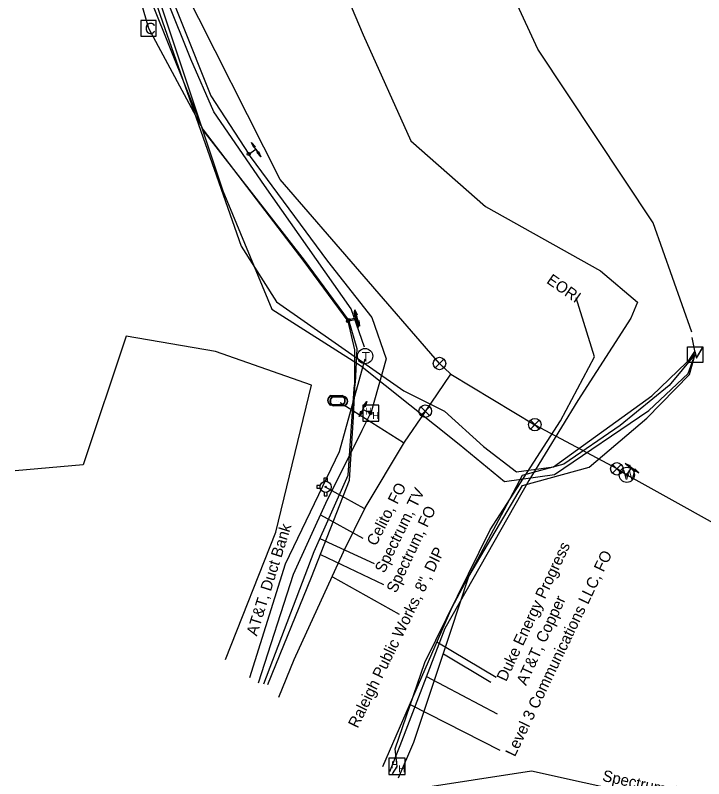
# Model space of a CAD drawing. Extents: x 2070721 to 2083039, y 729290 to 737883.
# Drawn here: x 2080202.5 to 2080447.3, y 733859.2 to 734130.6 of the extents above; entities that cross this region are included whole.
import ezdxf

# ---------------------------------------------------------------- set-up
doc = ezdxf.new("R2010")
doc.units = 0
for name, color, linetype in [('Cogo Default Point CELL', 7, 'Continuous'), ('COGO Default Point Elevation', 7, 'Continuous'), ('COGO Default Point Number', 7, 'Continuous'), ('Exist Utilities Gas UG Line SUE Cogo Point CELL', 7, 'Continuous'), ('Exist Utilities Gas UG Line SUE LOS B Cogo Comment', 7, 'Continuous'), ('Exist Utilities Gas Valve CELL', 7, 'Continuous'), ('Exist Utilities Gas Valve Cogo Elevation', 7, 'Continuous'), ('Exist Utilities Other Unknown UG SUE LOS B Cogo Comment', 7, 'Continuous'), ('Exist Utilities Other Unknown UG SUE LOS B Cogo Elevation', 7, 'Continuous'), ('Exist Utilities Power Pole CELL', 7, 'Continuous'), ('Exist Utilities Power Pole Cogo Elevation', 7, 'Continuous'), ('Exist Utilities Power UG Cable SUE LOS B Cogo Number', 7, 'Continuous'), ('Exist Utilities Telephone Hand Hole Cogo Elevation', 7, 'Continuous'), ('Exist Utilities Telephone Pedestal CELL', 7, 'Continuous'), ('Exist Utilities Telephone Pedestal Cogo Elevation', 7, 'Continuous'), ('Exist Utilities Telephone Pedestal Cogo Number', 7, 'Continuous'), ('Exist Utilities Telephone UG Cable Cogo Point CELL', 7, 'Continuous'), ('Exist Utilities Telephone UG Cable SUE LOS C Cogo Number', 7, 'Continuous'), ('Exist Utilities Telephone UG Cable SUE LOS C Cogo Point CELL', 7, 'Continuous'), ('Exist Utilities Telephone UG FO Cogo Point CELL', 7, 'Continuous'), ('Exist Utilities Telephone UG FO SUE LOS B Cogo Elevation', 7, 'Continuous'), ('Exist Utilities Telephone UG FO SUE LOS B Cogo Number', 7, 'Continuous'), ('Exist Utilities TV Hand Hole CELL', 7, 'Continuous'), ('Exist Utilities TV Pedestal CELL', 7, 'Continuous'), ('Exist Utilities TV Pedestal Cogo Elevation', 7, 'Continuous'), ('Exist Utilities TV UG Cable Cogo Point CELL', 7, 'Continuous'), ('Exist Utilities TV UG Cable SUE LOS C Cogo Comment', 7, 'Continuous'), ('Exist Utilities TV UG Cable SUE LOS C Cogo Elevation', 7, 'Continuous'), ('Exist Utilities TV UG Cable SUE LOS C Cogo Point CELL', 7, 'Continuous'), ('Exist Utilities Water Manhole CELL', 7, 'Continuous'), ('Exist Utilities Water Manhole Cogo Elevation', 7, 'Continuous'), ('Exist Utilities Water Meter CELL', 7, 'Continuous'), ('Exist Utilities Water Meter Cogo Number', 7, 'Continuous'), ('Exist Utilities Water UG Line SUE Cogo Point CELL', 7, 'Continuous'), ('Exist Utilities Water UG Line SUE LOS B Cogo Elevation', 7, 'Continuous'), ('Exist Utilities Water UG Line SUE LOS B Cogo Number', 7, 'Continuous'), ('Exist Utilities Water UG Line SUE LOS B Cogo Point CELL', 7, 'Continuous'), ('Exist Utilities Water Valve CELL', 7, 'Continuous'), ('Exist Utilities Water Valve Cogo Number', 7, 'Continuous')]:
    doc.layers.add(name, color=color, linetype=linetype)

msp = doc.modelspace()

# ---------------------------------------------------------------- linework, layer by layer
at = {"layer": 'Cogo Default Point CELL'}
msp.add_line((2080249.85, 734125.95), (2080249.85, 734125.95), dxfattribs=at)
msp.add_lwpolyline([(2080247.08, 734123.17), (2080252.63, 734123.17), (2080252.63, 734128.72), (2080247.08, 734128.72), (2080247.08, 734123.17)], dxfattribs=at)
at = {"layer": 'COGO Default Point Elevation'}
for points in [[(2080354.9, 734008.41), (2080351.75, 734005.26), (2080353.32, 734006.83), (2080354.9, 734005.26), (2080351.75, 734008.41)], [(2080349.82, 733991.44), (2080346.68, 733988.29), (2080348.25, 733989.86), (2080349.82, 733988.29), (2080346.68, 733991.44)], [(2080388.81, 733986.67), (2080385.67, 733983.52), (2080387.24, 733985.09), (2080388.81, 733983.52), (2080385.67, 733986.67)], [(2080417.94, 733970.95), (2080414.79, 733967.81), (2080416.36, 733969.38), (2080417.94, 733967.81), (2080414.79, 733970.95)]]:
    msp.add_lwpolyline(points, dxfattribs=at)
for centre in [(2080353.32, 734006.83), (2080348.25, 733989.86), (2080387.24, 733985.09), (2080416.36, 733969.38)]:
    msp.add_circle(centre, 2.23, dxfattribs=at)
at = {"layer": 'COGO Default Point Number'}
msp.add_line((2080312.85, 733962.96), (2080312.85, 733962.96), dxfattribs=at)
for points in [[(2080312.34, 733964.87), (2080312.34, 733966.16), (2080313.36, 733966.16), (2080313.36, 733964.85)], [(2080310.94, 733963.47), (2080309.65, 733963.47), (2080309.65, 733962.45), (2080310.94, 733962.45)], [(2080312.34, 733961.05), (2080312.34, 733959.76), (2080313.36, 733959.76), (2080313.36, 733961.07)]]:
    msp.add_lwpolyline(points, dxfattribs=at)
for radius in [1.98, 0.243]:
    msp.add_circle((2080312.85, 733962.96), radius, dxfattribs=at)
at = {"layer": 'Exist Utilities Gas Valve CELL'}
for p, q in [((2080352.43, 733907.84), (2080373.45, 733895.3)), ((2080354.76, 733903.61), (2080371.56, 733893.48))]:
    msp.add_line(p, q, dxfattribs=at)
at = {"layer": 'Exist Utilities Gas Valve Cogo Elevation'}
msp.add_line((2080348.73, 733895.58), (2080373.8, 733882.27), dxfattribs=at)
at = {"layer": 'Exist Utilities Other Unknown UG SUE LOS B Cogo Comment'}
msp.add_line((2080342.93, 733885.6), (2080374.73, 733869.31), dxfattribs=at)
at = {"layer": 'Exist Utilities Power Pole CELL'}
msp.add_lwpolyline([(2080285.9, 733895.15), (2080298.57, 733935.59), (2080317.74, 733975.49), (2080326.94, 734008.53)], dxfattribs=at)
at = {"layer": 'Exist Utilities Power Pole Cogo Elevation'}
for points in [[(2080225.45, 734168.4), (2080244.65, 734158.51), (2080253.95, 734130.69), (2080282.75, 734048.52), (2080295.34, 734028.75), (2080340.63, 733997.06), (2080355.06, 733989.84), (2080368.99, 733977.25), (2080380.73, 733968.31), (2080393.86, 733970.13), (2080428.86, 733995.36), (2080444.29, 734010.08)], [(2080277.17, 733901.6), (2080295.11, 733946.83), (2080307.81, 733999.15), (2080273.72, 734011.03), (2080241.89, 734016.58), (2080226.56, 733970.78), (2080202.47, 733968.66)], [(2080444.29, 734010.08), (2080435.02, 733998.98), (2080417.57, 733984.78), (2080397.54, 733970.98), (2080382.77, 733967.05), (2080376.16, 733954.67), (2080357.6, 733919.78), (2080333.03, 733863.36)]]:
    msp.add_lwpolyline(points, dxfattribs=at)
at = {"layer": 'Exist Utilities Power UG Cable SUE LOS B Cogo Number'}
for p, q in [((2080424.25, 733968), (2080419.3, 733971.32)), ((2080419.93, 733967.18), (2080421.65, 733969.74)), ((2080421.65, 733969.74), (2080424.25, 733968)), ((2080419.93, 733967.18), (2080419.93, 733967.18))]:
    msp.add_line(p, q, dxfattribs=at)
for points in [[(2080419.3, 733971.32), (2080421.13, 733970.5), (2080420.59, 733970.45), (2080420.74, 733969.99)], [(2080424.25, 733968), (2080422.42, 733968.81), (2080422.96, 733968.86), (2080422.82, 733969.33)]]:
    msp.add_lwpolyline(points, close=True, dxfattribs=at)
msp.add_circle((2080419.93, 733967.18), 0.517, dxfattribs=at)
at = {"layer": 'Exist Utilities Telephone Pedestal Cogo Elevation'}
msp.add_line((2080310.99, 733938.88), (2080333.44, 733928.18), dxfattribs=at)
at = {"layer": 'Exist Utilities Telephone UG Cable Cogo Point CELL'}
msp.add_line((2080338.22, 733863.58), (2080338.22, 733863.58), dxfattribs=at)
msp.add_lwpolyline([(2080335.34, 733860.7), (2080341.09, 733860.7), (2080341.09, 733866.45), (2080335.34, 733866.45), (2080335.34, 733860.7)], dxfattribs=at)
at = {"layer": 'Exist Utilities Telephone UG Cable SUE LOS C Cogo Number'}
msp.add_line((2080444.29, 734010.08), (2080444.29, 734010.08), dxfattribs=at)
msp.add_lwpolyline([(2080441.45, 734012.69), (2080447, 734012.69), (2080447, 734007.14), (2080441.45, 734007.14)], close=True, dxfattribs=at)
for points in [[(2080441.45, 734007.14), (2080444.09, 734011.08), (2080444.72, 734008.87), (2080447, 734012.69)], [(2080441.52, 734007.14), (2080444.09, 734010.87), (2080444.68, 734008.69), (2080447, 734012.54)]]:
    msp.add_lwpolyline(points, dxfattribs=at)
at = {"layer": 'Exist Utilities Telephone UG Cable SUE LOS C Cogo Point CELL'}
msp.add_circle((2080326.85, 734009.45), 2.72, dxfattribs=at)
at = {"layer": 'Exist Utilities Telephone UG FO Cogo Point CELL'}
for p, q in [((2080316.68, 733993.7), (2080316.68, 733993.7)), ((2080317.54, 733993.42), (2080317.54, 733993.42))]:
    msp.add_line(p, q, dxfattribs=at)
for points in [[(2080314.64, 733995.4), (2080318.72, 733995.4)], [(2080314.64, 733995.26), (2080318.72, 733995.26)], [(2080315.5, 733995.12), (2080319.58, 733995.12)], [(2080315.5, 733994.98), (2080319.58, 733994.98)], [(2080318.72, 733992.14), (2080314.62, 733992.14)], [(2080318.72, 733992), (2080314.62, 733992)], [(2080319.58, 733991.86), (2080315.48, 733991.86)], [(2080319.58, 733991.72), (2080315.48, 733991.72)]]:
    msp.add_lwpolyline(points, dxfattribs=at)
for centre, radius, start, end in [((2080315.37, 733993.69), 1.86, 113.178, 245.9794), ((2080315.38, 733993.69), 1.73, 115.3009, 243.7824), ((2080316.23, 733993.41), 1.86, 113.178, 245.9794), ((2080316.24, 733993.41), 1.73, 115.3009, 243.7824), ((2080317.97, 733993.7), 1.86, 293.6483, 66.3084), ((2080317.98, 733993.7), 1.73, 295.1272, 64.8728), ((2080318.83, 733993.42), 1.86, 293.6483, 66.3084), ((2080318.84, 733993.42), 1.73, 295.1272, 64.8728)]:
    msp.add_arc(centre, radius, start, end, dxfattribs=at)
at = {"layer": 'Exist Utilities Telephone UG FO SUE LOS B Cogo Elevation'}
msp.add_line((2080419.93, 733967.21), (2080419.93, 733967.21), dxfattribs=at)
msp.add_circle((2080419.93, 733967.22), 2.69, dxfattribs=at)
at = {"layer": 'Exist Utilities Telephone UG FO SUE LOS B Cogo Number'}
for p, q in [((2080326.08, 733992.03), (2080326.08, 733986.31)), ((2080331.8, 733992.03), (2080326.08, 733992.03)), ((2080331.8, 733986.31), (2080331.8, 733992.03)), ((2080328.94, 733989.17), (2080328.94, 733989.17)), ((2080326.08, 733986.31), (2080331.8, 733986.31))]:
    msp.add_line(p, q, dxfattribs=at)
at = {"layer": 'Exist Utilities TV Hand Hole CELL'}
msp.add_line((2080315.22, 733930.94), (2080339.02, 733917.7), dxfattribs=at)
at = {"layer": 'Exist Utilities TV Pedestal CELL'}
msp.add_lwpolyline([(2080321.01, 734022.31), (2080305.36, 734043.56), (2080269.25, 734089.82), (2080239.52, 734164.02)], dxfattribs=at)
at = {"layer": 'Exist Utilities TV Pedestal Cogo Elevation'}
for p, q in [((2080340.5, 733978.59), (2080318.05, 733992.79)), ((2080326.49, 733955.32), (2080312.83, 733962.88))]:
    msp.add_line(p, q, dxfattribs=at)
for points in [[(2080357.06, 734003.27), (2080353.32, 734006.79), (2080296.63, 734072.2), (2080261.95, 734141.13), (2080251.22, 734185.42), (2080250, 734189.2), (2080244.12, 734248.6), (2080244.13, 734251.5), (2080244.63, 734259.68), (2080245.13, 734264.1), (2080254.44, 734320.44), (2080276.53, 734380.91), (2080391.41, 734503.18), (2080497.9, 734548.7), (2080500.72, 734549.83), (2080585.45, 734578.7), (2080702.53, 734619.89), (2080710.17, 734622.62), (2080743.51, 734634.52), (2080754.26, 734638.28), (2080902.52, 734692.58), (2081024.44, 734735.33)], [(2080296.23, 733888.18), (2080301.7, 733901.61), (2080319.24, 733939.81), (2080326.85, 733955.51), (2080340.87, 733978.79), (2080348.3, 733989.77), (2080357.09, 734002.68), (2080357.34, 734003.04)], [(2080357.06, 734003.27), (2080357.34, 734003.04), (2080387.17, 733985.06), (2080416.62, 733969.4), (2080419.93, 733967.18)]]:
    msp.add_lwpolyline(points, dxfattribs=at)
at = {"layer": 'Exist Utilities TV UG Cable Cogo Point CELL'}
for points in [[(2080291.1, 734070.12), (2080273.08, 734096.26), (2080264.86, 734115.07), (2080247.85, 734157.71), (2080239.41, 734188.85), (2080232.9, 734211.26), (2080232.9, 734228.12), (2080231.97, 734244.9)], [(2080294.22, 734238.68), (2080294.22, 734221.46), (2080303.86, 734176.45), (2080326.14, 734123.68), (2080343.11, 734086.02), (2080369.71, 734062.6), (2080410.57, 734039.8), (2080423.78, 734028.65), (2080421.38, 734022.96), (2080402.46, 733993.71), (2080385.13, 733965.19), (2080355.27, 733912.59), (2080339.2, 733870.84), (2080335.53, 733861.67)], [(2080326.66, 734012.62), (2080321.93, 734026.22), (2080291.1, 734070.12)]]:
    msp.add_lwpolyline(points, dxfattribs=at)
at = {"layer": 'Exist Utilities TV UG Cable SUE LOS C Cogo Comment'}
msp.add_line((2080444.31, 734010.16), (2080443.13, 734016.08), dxfattribs=at)
for points in [[(2080234.72, 734179.83), (2080241.98, 734171.12), (2080276.22, 734068.16), (2080293.76, 734026.09), (2080325.21, 734006.15), (2080360.35, 733978.15), (2080376.41, 733964.84), (2080394.21, 733967.31), (2080427.72, 733990.11), (2080441.72, 734003.26), (2080444.29, 734010.08)], [(2080443.09, 734017.91), (2080429.26, 734056.79), (2080388.33, 734118.62), (2080372.45, 734153.12), (2080414.03, 734167.36)], [(2080338.76, 733859.49), (2080344.21, 733872.23), (2080357.27, 733911.24), (2080363.71, 733931.11), (2080382.81, 733963.43), (2080406.57, 733970.01), (2080426.99, 733987.33), (2080442.22, 734002.87), (2080444.29, 734010.08)]]:
    msp.add_lwpolyline(points, dxfattribs=at)
at = {"layer": 'Exist Utilities TV UG Cable SUE LOS C Cogo Elevation'}
for points in [[(2080228.33, 734237.2), (2080227.59, 734213.41), (2080238.77, 734164.01), (2080249.82, 734126.01), (2080269.26, 734089.95), (2080305.09, 734043.13), (2080320.73, 734021.92)], [(2080320.73, 734021.92), (2080323.11, 734011.73), (2080323.11, 733999.23)], [(2080290.82, 733892.89), (2080308.74, 733940.03), (2080320.87, 733967.1), (2080322.56, 733991.38), (2080323.11, 733999.23)]]:
    msp.add_lwpolyline(points, dxfattribs=at)
at = {"layer": 'Exist Utilities TV UG Cable SUE LOS C Cogo Point CELL'}
for points in [[(2080234.38, 734213.72), (2080251.15, 734154.39), (2080272, 734101.95), (2080285.47, 734081.3)], [(2080328.81, 733989.13), (2080325.75, 733983.01), (2080312.77, 733957.01), (2080301.25, 733931.83), (2080288.79, 733893.2)]]:
    msp.add_lwpolyline(points, dxfattribs=at)
at = {"layer": 'Exist Utilities Water Manhole CELL'}
msp.add_line((2080310.81, 733944.61), (2080330.1, 733935.71), dxfattribs=at)
at = {"layer": 'Exist Utilities Water Manhole Cogo Elevation'}
msp.add_line((2080310.98, 733953.01), (2080326.08, 733944.75), dxfattribs=at)
at = {"layer": 'Exist Utilities Water UG Line SUE Cogo Point CELL'}
for p, q in [((2080285.47, 734081.3), (2080288.06, 734082.98)), ((2080289.77, 734080.36), (2080286.51, 734085.35)), ((2080288.06, 734082.98), (2080289.77, 734080.36)), ((2080285.47, 734081.3), (2080285.47, 734081.3)), ((2080327.45, 733993.31), (2080324.79, 733987.98)), ((2080326.05, 733990.51), (2080327.45, 733993.31)), ((2080328.81, 733989.13), (2080326.05, 733990.51)), ((2080328.81, 733989.13), (2080328.81, 733989.13))]:
    msp.add_line(p, q, dxfattribs=at)
for points in [[(2080286.51, 734085.35), (2080287.88, 734083.89), (2080287.36, 734084.05), (2080287.31, 734083.57)], [(2080289.77, 734080.36), (2080288.41, 734081.82), (2080288.92, 734081.66), (2080288.97, 734082.14)], [(2080327.45, 733993.31), (2080326.88, 733991.4), (2080326.76, 733991.93), (2080326.31, 733991.72)], [(2080324.79, 733987.98), (2080325.36, 733989.9), (2080325.48, 733989.37), (2080325.92, 733989.57)]]:
    msp.add_lwpolyline(points, close=True, dxfattribs=at)
for centre in [(2080285.47, 734081.3), (2080328.81, 733989.13)]:
    msp.add_circle(centre, 0.517, dxfattribs=at)
at = {"layer": 'Exist Utilities Water UG Line SUE LOS B Cogo Elevation'}
for points in [[(2080321.01, 734022.31), (2080323.92, 734012.13), (2080323.35, 733999.94)], [(2080292.27, 733892.65), (2080307.82, 733930.84), (2080321.29, 733965.32), (2080322.78, 733987.76), (2080323.02, 733992.9), (2080323.35, 733999.94)], [(2080344.57, 733855.58), (2080386, 733861.95), (2080496.25, 733837.52)]]:
    msp.add_lwpolyline(points, dxfattribs=at)
at = {"layer": 'Exist Utilities Water UG Line SUE LOS B Cogo Number'}
for points in [[(2080285.47, 734081.3), (2080286.04, 734080.39), (2080313.44, 734043.19), (2080329.21, 734023.2), (2080334.41, 734008.43), (2080328.94, 733989.17)], [(2080336.57, 733860.97), (2080338.22, 733863.58), (2080337.51, 733869.77), (2080348.05, 733900.55), (2080371.36, 733947.72), (2080396.33, 733986.42), (2080408.45, 734009.24), (2080401.96, 734030.18)]]:
    msp.add_lwpolyline(points, dxfattribs=at)
at = {"layer": 'Exist Utilities Water UG Line SUE LOS B Cogo Point CELL'}
msp.add_lwpolyline([(2080419.93, 733967.18), (2080512.22, 733915.86), (2080684.81, 733822.52), (2080926.94, 733749.77), (2081207.6, 733698.37)], dxfattribs=at)
at = {"layer": 'Exist Utilities Water Valve CELL'}
for p, q in [((2080324.45, 734019.56), (2080323.09, 734025.37)), ((2080324.83, 734020.14), (2080323.2, 734025.87)), ((2080320.73, 734021.92), (2080323.73, 734022.62)), ((2080320.73, 734021.92), (2080320.73, 734021.92)), ((2080321.01, 734022.31), (2080323.97, 734023.16)), ((2080321.01, 734022.31), (2080321.01, 734022.31)), ((2080323.73, 734022.62), (2080324.45, 734019.56)), ((2080323.97, 734023.16), (2080324.83, 734020.14))]:
    msp.add_line(p, q, dxfattribs=at)
for points in [[(2080323.09, 734025.37), (2080323.87, 734023.53), (2080323.44, 734023.86), (2080323.23, 734023.42)], [(2080323.2, 734025.87), (2080324.07, 734024.07), (2080323.62, 734024.38), (2080323.43, 734023.93)], [(2080324.45, 734019.56), (2080323.67, 734021.4), (2080324.1, 734021.07), (2080324.31, 734021.52)], [(2080324.83, 734020.14), (2080323.96, 734021.94), (2080324.41, 734021.63), (2080324.6, 734022.08)]]:
    msp.add_lwpolyline(points, close=True, dxfattribs=at)
for centre in [(2080320.73, 734021.92), (2080321.01, 734022.31)]:
    msp.add_circle(centre, 0.517, dxfattribs=at)

# ---------------------------------------------------------------- texts
at = {"layer": 'Cogo Default Point CELL'}
msp.add_text('C', height=4, dxfattribs=at).set_placement((2080248.54, 734123.95))
at = {"layer": 'Exist Utilities Gas UG Line SUE Cogo Point CELL'}
msp.add_text('Raleigh Public Works, 8", DIP ', height=4, rotation=63.943, dxfattribs=at).set_placement((2080324.23, 733876.88))
at = {"layer": 'Exist Utilities Gas UG Line SUE LOS B Cogo Comment'}
msp.add_text('Celito, FO ', height=4, rotation=63.0173, dxfattribs=at).set_placement((2080330.74, 733941.66))
at = {"layer": 'Exist Utilities Other Unknown UG SUE LOS B Cogo Elevation'}
msp.add_text('Level 3 Communications LLC, FO', height=4, rotation=64.369, dxfattribs=at).set_placement((2080380.12, 733866.75))
at = {"layer": 'Exist Utilities Telephone Hand Hole Cogo Elevation'}
msp.add_text('Spectrum, TV ', height=4, rotation=63.7218, dxfattribs=at).set_placement((2080333.68, 733932.01))
at = {"layer": 'Exist Utilities Telephone Pedestal CELL'}
for s, rotation, p in [('Spectrum, FO ', 64.5306, (2080337.86, 733924.92)), ('Spectrum, FO', 347.5069, (2080410.99, 733858.46))]:
    msp.add_text(s, height=4, rotation=rotation, dxfattribs=at).set_placement(p)
at = {"layer": 'Exist Utilities Telephone Pedestal Cogo Number'}
msp.add_text('AT&T, Duct Bank', height=4, rotation=72.6064, dxfattribs=at).set_placement((2080288.36, 733909.7))
at = {"layer": 'Exist Utilities Telephone UG Cable Cogo Point CELL'}
for p in [(2080336.13, 733862.93), (2080338.7, 733861.47)]:
    msp.add_text('H', height=2.5, dxfattribs=at).set_placement(p)
at = {"layer": 'Exist Utilities Telephone UG Cable SUE LOS C Cogo Point CELL'}
msp.add_text('T', height=3.5, dxfattribs=at).set_placement((2080325.68, 734007.44))
at = {"layer": 'Exist Utilities Telephone UG FO SUE LOS B Cogo Elevation'}
msp.add_text('W', height=3.5, dxfattribs=at).set_placement((2080418.58, 733965.46))
at = {"layer": 'Exist Utilities Telephone UG FO SUE LOS B Cogo Number'}
for p in [(2080326.86, 733988.58), (2080329.43, 733987.11)]:
    msp.add_text('H', height=2.5, dxfattribs=at).set_placement(p)
at = {"layer": 'Exist Utilities Water Meter CELL'}
msp.add_text('Duke Energy Progress', height=4, rotation=64.8519, dxfattribs=at).set_placement((2080377.02, 733893.48))
at = {"layer": 'Exist Utilities Water Meter Cogo Number'}
msp.add_text('AT&T, Copper', height=4, rotation=65.3806, dxfattribs=at).set_placement((2080384.1, 733892.04))
at = {"layer": 'Exist Utilities Water Valve Cogo Number'}
msp.add_text('EORI', height=4, rotation=325.1618, dxfattribs=at).set_placement((2080391.09, 734035.64))

doc.saveas('drawing.dxf')
